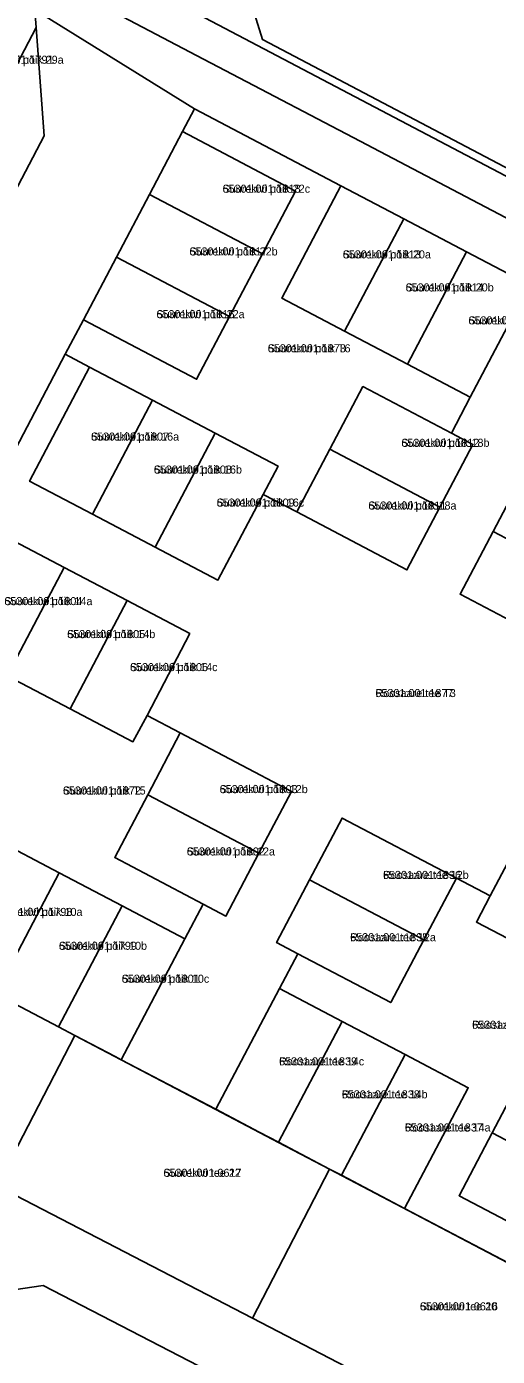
# Model space of a CAD drawing. Extents: x 543236 to 563717, y 6566033 to 6588992.
# Drawn here: x 545789.8 to 545877.3, y 6584851 to 6585098.7 of the extents above; entities that cross this region are included whole.
import ezdxf

# ---------------------------------------------------------------- set-up
doc = ezdxf.new("R2010")
doc.units = 0
for name, color, linetype in [('L_AADRESS', 7, 'Continuous'), ('PIIR', 7, 'Continuous'), ('TUNNUS', 7, 'Continuous')]:
    doc.layers.add(name, color=color, linetype=linetype)

msp = doc.modelspace()

# ---------------------------------------------------------------- linework, layer by layer
at = {"layer": 'PIIR'}
for points in [[(545833.08, 6585146.15), (545992.67, 6585063.45), (545971.92, 6585023.44), (545833.63, 6585096.27), (545823.69, 6585128.22)], [(545812.07, 6585106.08), (545823.69, 6585128.22), (545833.63, 6585096.27), (545971.92, 6585023.44), (546022.77, 6584996.72), (546073.26, 6584970.13), (546133.17, 6584938.54), (546131.11, 6584938.14)], [(545781.2, 6585107.22), (545791.29, 6585101.79), (545791.54, 6585098.53), (545780.68, 6585077.87), (545768.99, 6585084.02)], [(545805.7, 6585107.83), (545811.43, 6585104.81), (545812.07, 6585106.08), (546131.11, 6584938.14), (546133.17, 6584938.54), (546136.79, 6584939.31), (546134.3, 6584928.75), (546078.99, 6584957.84), (546025.89, 6584985.76), (545964.63, 6585017.97), (545933.81, 6585034.18), (545906.53, 6585048.53), (545879.98, 6585062.49), (545851.77, 6585077.33), (545826.71, 6585090.51), (545821.39, 6585093.3), (545808.87, 6585099.89), (545803.14, 6585102.9)], [(545820.99, 6585083.38), (545848.23, 6585069.05), (545837.23, 6585048.13), (545848.91, 6585041.99), (545860.6, 6585035.84), (545872.28, 6585029.7), (545868.76, 6585023), (545852.3, 6585031.66), (545846.15, 6585019.98), (545840.01, 6585008.3), (545833.76, 6585011.58), (545836.53, 6585016.85), (545824.85, 6585023), (545813.17, 6585029.14), (545801.48, 6585035.29), (545796.96, 6585037.66), (545800.33, 6585044.08), (545821.37, 6585033.01), (545827.51, 6585044.69), (545833.66, 6585056.38), (545839.8, 6585068.06), (545818.76, 6585079.13)], [(545818.76, 6585079.13), (545839.8, 6585068.06), (545833.66, 6585056.38), (545812.61, 6585067.44)], [(545848.23, 6585069.05), (545859.91, 6585062.9), (545848.91, 6585041.99), (545837.23, 6585048.13)], [(545812.61, 6585067.44), (545833.66, 6585056.38), (545827.51, 6585044.69), (545806.47, 6585055.76)], [(545859.91, 6585062.9), (545871.59, 6585056.76), (545860.6, 6585035.84), (545848.91, 6585041.99)], [(545871.59, 6585056.76), (545883.28, 6585050.61), (545872.28, 6585029.7), (545860.6, 6585035.84)], [(545806.47, 6585055.76), (545827.51, 6585044.69), (545821.37, 6585033.01), (545800.33, 6585044.08)], [(545801.48, 6585035.29), (545813.17, 6585029.14), (545802, 6585007.9), (545790.31, 6585014.03)], [(545852.3, 6585031.66), (545868.76, 6585023), (545872.78, 6585020.89), (545866.64, 6585009.2), (545846.15, 6585019.98)], [(545813.17, 6585029.14), (545824.85, 6585023), (545813.68, 6585001.76), (545802, 6585007.9)], [(545824.85, 6585023), (545836.53, 6585016.85), (545833.76, 6585011.58), (545825.36, 6584995.61), (545813.68, 6585001.76)], [(545846.15, 6585019.98), (545866.64, 6585009.2), (545860.5, 6584997.52), (545840.01, 6585008.3)], [(545882.65, 6585016.34), (545887.43, 6585013.82), (545903.89, 6585005.16), (545897.75, 6584993.48), (545876.51, 6585004.65)], [(545876.51, 6585004.65), (545897.75, 6584993.48), (545891.61, 6584981.8), (545870.37, 6584992.97)], [(545785.08, 6585004.08), (545796.76, 6584997.94), (545786.18, 6584977.81), (545774.49, 6584983.96)], [(545796.76, 6584997.94), (545808.44, 6584991.8), (545797.86, 6584971.67), (545786.18, 6584977.81)], [(545808.44, 6584991.8), (545820.12, 6584985.65), (545812.16, 6584970.38), (545809.54, 6584965.52), (545797.86, 6584971.67)], [(545770.02, 6584986.31), (545774.49, 6584983.96), (545786.18, 6584977.81), (545797.86, 6584971.67), (545809.54, 6584965.52), (545812.16, 6584970.38), (545818.3, 6584967.15), (545812.3, 6584955.61), (545806.16, 6584943.93), (545822.62, 6584935.28), (545819.22, 6584928.8), (545807.53, 6584934.94), (545795.85, 6584941.09), (545783.53, 6584947.57), (545771.69, 6584925.06), (545758.92, 6584931.78), (545745.2, 6584938.99), (545748.38, 6584945.04), (545769.32, 6584934.03), (545775.46, 6584945.71), (545781.6, 6584957.4), (545787.75, 6584969.08), (545766.77, 6584980.11)], [(545818.3, 6584967.15), (545839.01, 6584956.26), (545832.97, 6584944.74), (545812.3, 6584955.61)], [(545812.3, 6584955.61), (545832.97, 6584944.74), (545826.84, 6584933.05), (545822.62, 6584935.28), (545806.16, 6584943.93)], [(545848.44, 6584951.3), (545869.69, 6584940.12), (545863.63, 6584928.61), (545842.39, 6584939.78)], [(545884.01, 6584952.05), (545895.66, 6584945.93), (545885.07, 6584925.8), (545873.42, 6584931.93), (545875.99, 6584936.81)], [(545783.53, 6584947.57), (545795.85, 6584941.09), (545784.01, 6584918.58), (545771.69, 6584925.06)], [(545795.85, 6584941.09), (545807.53, 6584934.94), (545795.7, 6584912.44), (545784.01, 6584918.58)], [(545840.18, 6584926.03), (545857.49, 6584916.93), (545863.63, 6584928.61), (545869.69, 6584940.12), (545875.99, 6584936.81), (545873.42, 6584931.93), (545885.07, 6584925.8), (545896.76, 6584919.65), (545908.44, 6584913.51), (545905.18, 6584907.31), (545888.64, 6584916.01), (545882.5, 6584904.33), (545876.35, 6584892.65), (545870.21, 6584880.96), (545891.45, 6584869.79), (545888.28, 6584863.76), (545884.56, 6584865.71), (545860.07, 6584878.59), (545871.9, 6584901.09), (545860.15, 6584907.27), (545848.46, 6584913.42), (545836.78, 6584919.56)], [(545842.39, 6584939.78), (545863.63, 6584928.61), (545857.49, 6584916.93), (545840.18, 6584926.03), (545836.25, 6584928.1)], [(545807.53, 6584934.94), (545819.22, 6584928.8), (545807.36, 6584906.26), (545806.22, 6584906.87), (545798.75, 6584910.83), (545795.7, 6584912.44)], [(545758.92, 6584931.78), (545771.69, 6584925.06), (545784.01, 6584918.58), (545795.7, 6584912.44), (545798.75, 6584910.83), (545784.21, 6584882.82), (545780.78, 6584884.6), (545771.68, 6584882.57), (545741.51, 6584898.23)], [(545836.78, 6584919.56), (545848.46, 6584913.42), (545836.63, 6584890.92), (545833.03, 6584892.81), (545824.95, 6584897.06)], [(545848.46, 6584913.42), (545860.15, 6584907.27), (545848.32, 6584884.77), (545846.1, 6584885.93), (545836.63, 6584890.92)], [(545798.75, 6584910.83), (545807.36, 6584906.26), (545824.95, 6584897.05), (545836.63, 6584890.91), (545846.1, 6584885.93), (545831.75, 6584858.15), (545784.21, 6584882.82)], [(545860.15, 6584907.27), (545871.9, 6584901.09), (545860.07, 6584878.59), (545848.32, 6584884.77)], [(545882.5, 6584904.33), (545903.74, 6584893.16), (545897.59, 6584881.48), (545876.35, 6584892.65)], [(545876.35, 6584892.65), (545897.59, 6584881.48), (545891.45, 6584869.79), (545870.21, 6584880.96)], [(545846.1, 6584885.93), (545893.9, 6584860.8), (545879.63, 6584833.3), (545847.67, 6584849.89), (545831.75, 6584858.15)], [(545778.52, 6584862.12), (545792.82, 6584864.27), (545830.82, 6584844.55), (545817.69, 6584819.25), (545787.51, 6584834.92), (545769.3, 6584844.37)]]:
    msp.add_lwpolyline(points, close=True, dxfattribs=at)
for points in [[(545786.77, 6585066.38), (545793.06, 6585078.35), (545791.54, 6585098.53), (545791.29, 6585101.79), (545820.99, 6585083.38), (545818.76, 6585079.13), (545812.61, 6585067.44), (545806.47, 6585055.76), (545800.33, 6585044.08), (545796.96, 6585037.66), (545770.02, 6584986.31)], [(546074.81, 6584949.89), (546035.84, 6584970.39), (546018.31, 6584979.6), (546000.79, 6584988.82), (545973.17, 6585003.34), (545964.17, 6585008.07), (545936.73, 6585022.5), (545925.05, 6585028.64), (545913.37, 6585034.79), (545901.69, 6585040.93), (545883.28, 6585050.61), (545871.59, 6585056.76), (545859.91, 6585062.9), (545848.23, 6585069.05), (545820.99, 6585083.38), (545791.29, 6585101.79)], [(545780.68, 6585077.87), (545791.54, 6585098.53), (545793.06, 6585078.35), (545786.77, 6585066.38)], [(545808.87, 6585099.89), (545821.39, 6585093.3), (545826.71, 6585090.51), (545851.77, 6585077.33), (545879.98, 6585062.49), (545906.53, 6585048.53), (545933.81, 6585034.18), (545964.63, 6585017.97), (546025.89, 6584985.76), (546078.99, 6584957.84)], [(545770.02, 6584986.31), (545796.96, 6585037.66), (545801.48, 6585035.29), (545790.31, 6585014.03), (545802, 6585007.9), (545813.68, 6585001.76), (545825.36, 6584995.61), (545833.76, 6585011.58), (545840.01, 6585008.3), (545860.5, 6584997.52), (545866.64, 6585009.2), (545872.78, 6585020.89), (545868.76, 6585023), (545872.28, 6585029.7), (545883.28, 6585050.61)], [(545882.65, 6585016.34), (545876.51, 6585004.65), (545870.37, 6584992.97), (545891.61, 6584981.8)], [(545884.01, 6584952.05), (545875.99, 6584936.81), (545869.69, 6584940.12), (545848.44, 6584951.3), (545842.39, 6584939.78), (545836.25, 6584928.1), (545840.18, 6584926.03), (545836.78, 6584919.56), (545824.95, 6584897.06), (545807.36, 6584906.26), (545819.22, 6584928.8), (545822.62, 6584935.28), (545826.84, 6584933.05), (545832.97, 6584944.74), (545839.01, 6584956.26), (545818.3, 6584967.15), (545812.16, 6584970.38), (545820.12, 6584985.65), (545808.44, 6584991.8), (545796.76, 6584997.94), (545785.08, 6585004.08)], [(545784.21, 6584882.82), (545831.75, 6584858.15), (545847.67, 6584849.89)], [(545767.25, 6584795.86), (545792.1, 6584782.96), (545794.4, 6584787.4), (545799.73, 6584784.64), (545817.69, 6584819.25), (545830.82, 6584844.55), (545792.82, 6584864.27), (545778.52, 6584862.12)]]:
    msp.add_lwpolyline(points, dxfattribs=at)

# ---------------------------------------------------------------- texts
at = {"layer": 'L_AADRESS'}
for s, p in [('Suurekivi põik 29a', (545780.27, 6585091.77)), ('Suurekivi põik 22c', (545826.21, 6585067.75)), ('Suurekivi põik 22b', (545820.06, 6585056.07)), ('Suurekivi põik 20a', (545848.57, 6585055.52)), ('Suurekivi põik 20b', (545860.25, 6585049.37)), ('Suurekivi põik 22a', (545813.92, 6585044.39)), ('Suurekivi põik 20c', (545871.94, 6585043.23)), ('Suurekivi põik T6', (545834.62, 6585038.03)), ('Suurekivi põik 16a', (545801.74, 6585021.59)), ('Suurekivi põik 18b', (545859.46, 6585020.43)), ('Suurekivi põik 16b', (545813.43, 6585015.45)), ('Suurekivi põik 16c', (545825.11, 6585009.3)), ('Suurekivi põik 18a', (545853.32, 6585008.75)), ('Suurekivi põik 14a', (545785.62, 6584990.95)), ('Suurekivi põik 14b', (545797.31, 6584984.81)), ('Suurekivi põik 14c', (545808.99, 6584978.66)), ('Roosaare tee T3', (545854.64, 6584973.83)), ('Suurekivi põik 12b', (545825.66, 6584955.94)), ('Suurekivi põik T5', (545796.52, 6584955.68)), ('Suurekivi põik 12a', (545819.56, 6584944.33)), ('Roosaare tee 12b', (545856.04, 6584939.96)), ('Suurekivi põik 10a', (545783.77, 6584933.07)), ('Suurekivi põik 10b', (545795.77, 6584926.76)), ('Roosaare tee 12a', (545849.94, 6584928.36)), ('Suurekivi põik 10c', (545807.46, 6584920.63)), ('Roosaare tee T2', (545872.61, 6584912.06)), ('Roosaare tee 14c', (545836.71, 6584905.24)), ('Roosaare tee 14b', (545848.39, 6584899.1)), ('Roosaare tee 14a', (545860.11, 6584892.93)), ('Suurekivi tee 22', (545815.22, 6584884.49)), ('Suurekivi tee 20', (545862.9, 6584859.62))]:
    msp.add_text(s, height=1.5, dxfattribs=at).set_placement(p)
at = {"layer": 'TUNNUS'}
for s, p in [('65301:001:1791', (545780.27, 6585091.77)), ('65301:001:1818', (545826.21, 6585067.75)), ('65301:001:1817', (545820.06, 6585056.07)), ('65301:001:1813', (545848.57, 6585055.52)), ('65301:001:1814', (545860.25, 6585049.37)), ('65301:001:1816', (545813.92, 6585044.39)), ('65301:001:1815', (545871.94, 6585043.23)), ('65301:001:1873', (545834.62, 6585038.03)), ('65301:001:1807', (545801.74, 6585021.59)), ('65301:001:1812', (545859.46, 6585020.43)), ('65301:001:1808', (545813.43, 6585015.45)), ('65301:001:1809', (545825.11, 6585009.3)), ('65301:001:1811', (545853.32, 6585008.75)), ('65301:001:1804', (545785.62, 6584990.95)), ('65301:001:1805', (545797.31, 6584984.81)), ('65301:001:1806', (545808.99, 6584978.66)), ('65301:001:1877', (545854.64, 6584973.83)), ('65301:001:1803', (545825.66, 6584955.94)), ('65301:001:1872', (545796.52, 6584955.68)), ('65301:001:1802', (545819.56, 6584944.33)), ('65301:001:1836', (545856.04, 6584939.96)), ('65301:001:1798', (545783.77, 6584933.07)), ('65301:001:1799', (545795.77, 6584926.76)), ('65301:001:1835', (545849.94, 6584928.36)), ('65301:001:1801', (545807.46, 6584920.63)), ('65301:001:1876', (545872.61, 6584912.06)), ('65301:001:1839', (545836.71, 6584905.24)), ('65301:001:1838', (545848.39, 6584899.1)), ('65301:001:1837', (545860.11, 6584892.93)), ('65301:001:0617', (545815.22, 6584884.49)), ('65301:001:0616', (545862.9, 6584859.62))]:
    msp.add_text(s, height=1.5, dxfattribs=at).set_placement(p)

doc.saveas('drawing.dxf')
